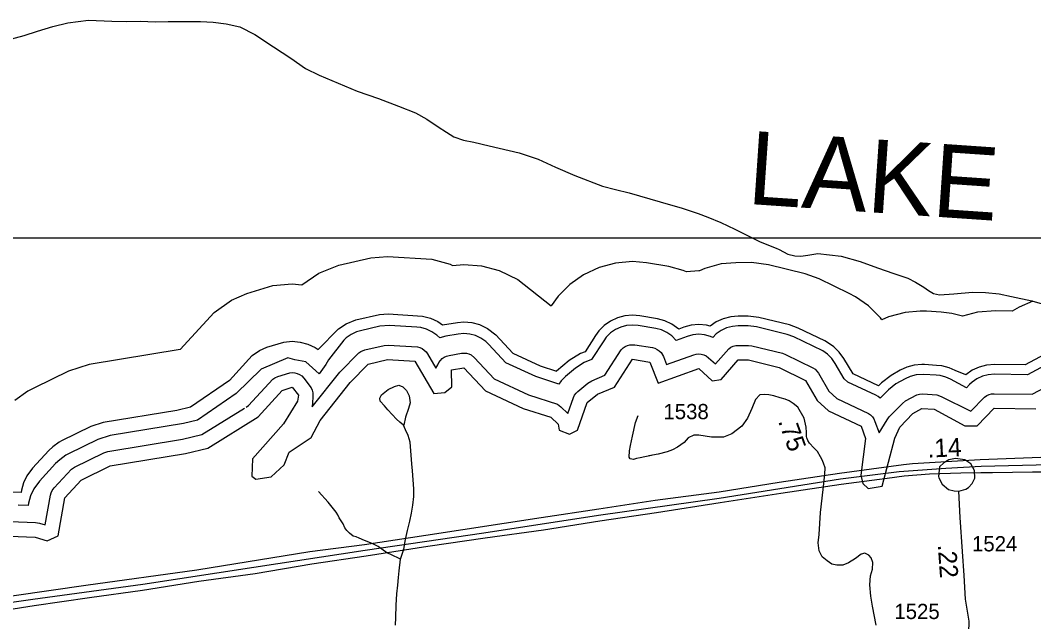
# Model space of a CAD drawing. Extents: x 2290615 to 2522933, y 819489 to 1012715.
# Drawn here: x 2377563 to 2385868, y 993811 to 998744 of the extents above; entities that cross this region are included whole.
import ezdxf

# ---------------------------------------------------------------- set-up
doc = ezdxf.new("R2010")
doc.units = 0
for name, color, linetype in [('Exist Boundary Political CountyLine', 7, 'Continuous'), ('Exist Hydrographic Buffer Line', 7, 'Continuous'), ('Exist Hydrographic Lake Shore', 7, 'Continuous'), ('Exist Hydrographic Lake Shore Label', 7, 'Continuous'), ('Exist Road Non-System Type 51', 7, 'Continuous'), ('Exist Road Secondary Mileage Tenths English Label', 7, 'Continuous'), ('Exist Road Secondary Type 51 Attributed', 7, 'Continuous'), ('Exist Road Secondary Type 51 Number Label', 7, 'Continuous'), ('Exist Utilities Electrical Transmission Line', 7, 'Continuous'), ('Map Preparation Inset Cut Line', 7, 'Continuous')]:
    doc.layers.add(name, color=color, linetype=linetype)

msp = doc.modelspace()

# ---------------------------------------------------------------- linework, layer by layer
at = {"layer": 'Exist Boundary Political CountyLine'}
msp.add_lwpolyline([(2377454.4, 998580.3), (2377594.9, 998620.1), (2377703.5, 998654.6), (2377830, 998693.8), (2377952.9, 998722.9), (2378122.1, 998743.8), (2378312.5, 998737.7), (2378430.7, 998734.5), (2378546.7, 998735.3), (2378671, 998730.4), (2378775, 998732.7), (2378927.1, 998732.9), (2379039.1, 998733.5), (2379145.4, 998727.9), (2379252, 998714.3), (2379363.1, 998688.8), (2379485.8, 998625.8), (2379638, 998526), (2379781.9, 998433.9), (2379901.4, 998348.7), (2380013.8, 998293.3), (2380325.4, 998162), (2380497.9, 998103.1), (2380662.6, 998039.8), (2380801, 997983.5), (2380895.1, 997933.3), (2380987.8, 997869.1), (2381055.7, 997825.8), (2381115.2, 997788.3), (2381196.4, 997761.6), (2381279.2, 997743), (2381406.5, 997714.2), (2381653, 997656.3), (2381807.2, 997604.6), (2381950, 997538.4), (2382106.9, 997470.8), (2382334.7, 997382.1), (2382439.8, 997356.4), (2382553, 997329.1), (2382806.3, 997253.4), (2382988.5, 997202.9), (2383118.3, 997160.2), (2383197.6, 997129.4), (2383305.5, 997083.9), (2383417.8, 997030.4), (2383626.2, 996926.9), (2383756.4, 996874.3), (2383780.9, 996863.3), (2383854.5, 996826.3), (2383911.2, 996810.6), (2383959.3, 996808.6), (2384017, 996816.9), (2384098.4, 996832.3), (2384291.4, 996810.2), (2384445.4, 996764.5), (2384587.5, 996714.3), (2384721.6, 996665.8), (2384837.2, 996628.5), (2384900.6, 996595.1), (2384968.3, 996555.9), (2385005.5, 996527.4), (2385046.5, 996503.1), (2385047.5, 996502.9), (2385097, 996491.1), (2385214.7, 996500), (2385366.2, 996514.2), (2385472.4, 996510.6), (2385584.9, 996501.2), (2385685.9, 996477.3), (2385851.5, 996442.1), (2386260.6, 996324.8)], dxfattribs=at)
at = {"layer": 'Exist Hydrographic Buffer Line'}
for points in [[(2378874.5, 996043.8), (2379151.5, 996348.1), (2379293.4, 996446.9), (2379420.5, 996502.8), (2379631.9, 996567.6), (2379792.2, 996581.9), (2379871.6, 996574.8), (2380009.7, 996671), (2380172.7, 996735.4), (2380436, 996795.5), (2380574, 996806.4), (2380935.7, 996783.3), (2381085.6, 996743.2), (2381106.7, 996733.4), (2381197.7, 996741.2), (2381343.9, 996728.9), (2381486.7, 996690.7), (2381642, 996618.9), (2381912.7, 996402.4)], [(2385556.4, 996361.2), (2385406.4, 996349.3), (2385284.5, 996316.8), (2385197.1, 996340.1), (2385110.8, 996350.2), (2384990.7, 996357.1), (2384938.6, 996358.4), (2384814, 996347.5), (2384679.4, 996311.7), (2384624.3, 996286.2), (2384611.8, 996303.9), (2384513.5, 996402.5), (2384408.4, 996475.9), (2384355.1, 996504.3), (2384109, 996623.9), (2383994.5, 996665.1), (2383695.6, 996738.9), (2383555.5, 996755.9), (2383426.3, 996755.6), (2383308.2, 996745), (2383173.7, 996709.1), (2383128.2, 996687.8), (2383123.3, 996688.2), (2383023.8, 996679.4), (2382995.8, 996692.5), (2382877.5, 996724.1), (2382693.8, 996754.7), (2382579.5, 996764.2), (2382441.8, 996752.2), (2382306.7, 996716.1), (2382180.2, 996657), (2382066.1, 996577), (2381971.3, 996482.2), (2381912.7, 996402.4)], [(2385860.6, 996439.5), (2385748.8, 996389.6), (2385691.2, 996359), (2385556.4, 996361.2)], [(2379276.7, 995788.9), (2379462.8, 995993.3), (2379524, 996035.9), (2379584.2, 996062.4), (2379722.3, 996104.7), (2379792.2, 996110.9), (2379857.6, 996105.1), (2379920.4, 996088.3), (2379979.7, 996060.9), (2380005, 996043.2), (2380172.1, 996212.4), (2380233, 996254.8), (2380311.9, 996286), (2380507, 996330.5), (2380577.5, 996336.1), (2380859.4, 996318.2), (2380925.3, 996300.5), (2380984.6, 996273.1), (2381024.6, 996245.3), (2381145.5, 996265.9), (2381198.1, 996270.5), (2381263, 996265), (2381326.4, 996248), (2381393.5, 996217), (2381459.8, 996163.9), (2381599.7, 996014), (2381822.9, 995909.9), (2381958, 995866.2)], [(2385549.2, 995921.3), (2385480.8, 995915.8), (2385420.1, 995899.6), (2385363.3, 995873.1), (2385311.8, 995837.1), (2385224.5, 995870.3), (2385175.5, 995892.5), (2385114.8, 995908.7), (2385072.7, 995913.7), (2384972.7, 995919.4), (2384952.2, 995919.9), (2384889.8, 995914.5), (2384828.9, 995898.3), (2384775, 995873.3), (2384700, 995830.8), (2384619.8, 995769.2), (2384596.8, 995745.5), (2384389.1, 995843.8), (2384311.6, 995969.3), (2384275.1, 996021.3), (2384230.8, 996065.7), (2384179.3, 996101.7), (2384156.6, 996113.8), (2383938.6, 996219.7), (2383867.4, 996245.3), (2383616.5, 996307.3), (2383529.5, 996317.8), (2383446.5, 996317.6), (2383384.8, 996312.1), (2383324.1, 996295.9), (2383267.3, 996269.3), (2383217.4, 996234.6), (2383185.9, 996243), (2383123.3, 996248.5), (2383060.8, 996243), (2383000.1, 996226.8), (2382958.7, 996211.6), (2382902.3, 996252.7), (2382845.5, 996279.3), (2382784.8, 996295.5), (2382639.6, 996319.7), (2382580.3, 996324.6), (2382517.8, 996319.2), (2382457.1, 996303), (2382400.3, 996276.4), (2382348.8, 996240.3), (2382304.5, 996196), (2382277.3, 996158.9), (2382191.3, 996024.8), (2382154.8, 996009.7), (2382060.3, 995952.4), (2381958, 995866.2)], [(2382030, 995822.1), (2381995.7, 995788), (2381976.5, 995760.5), (2381787.8, 995821.3), (2381543, 995935.7), (2381402.9, 996085.6), (2381378.3, 996109.1), (2381338.3, 996137.1), (2381294, 996157.7), (2381246.7, 996170.3), (2381198.3, 996174.6), (2381150.7, 996170.5), (2381050.8, 996153.4), (2381002.5, 996140.6), (2380977.2, 996161.6), (2380937.2, 996189.6), (2380893, 996210.2), (2380845.8, 996222.8), (2380814.2, 996226.6), (2380589.3, 996240.3), (2380509.9, 996233.8), (2380352, 996197.7), (2380318.6, 996187.8), (2380274.3, 996167.2), (2380234.3, 996139.2), (2380214.4, 996121), (2380088.9, 995959.7), (2380067.5, 995920.4), (2380013.9, 995845.4), (2379903.2, 995941.9), (2379813.9, 995959.7), (2379756.7, 995974), (2379538.8, 995881.1), (2379333.6, 995682.3)], [(2385993.4, 995930.8), (2385817.5, 995836.9), (2385547.8, 995841.3), (2385494.7, 995837.1), (2385447.6, 995824.5), (2385403.3, 995803.9), (2385363.3, 995775.9), (2385342, 995756.1), (2385316.3, 995729.3), (2385186.3, 995800.1), (2385148, 995817.4), (2385100.8, 995830), (2385068.2, 995833.8), (2384968.2, 995839.5), (2384903.8, 995835.8), (2384856.6, 995823), (2384814.2, 995803.7), (2384739.3, 995761.2), (2384677, 995713.2), (2384611, 995645.6), (2384594.4, 995657.3), (2384574.1, 995667.9), (2384344, 995776.7), (2384314.3, 995803.9), (2384242.1, 995929.5), (2384213.8, 995970), (2384179.3, 996004.4), (2384139.3, 996032.4), (2383903.7, 996147.7), (2383848.2, 996167.7), (2383597.2, 996229.7), (2383529.5, 996237.9), (2383446.5, 996237.7), (2383398.7, 996233.3), (2383351.5, 996220.7), (2383307.2, 996200.1), (2383267.3, 996172.1), (2383237.5, 996143), (2383219.1, 996151.6), (2383171.7, 996164.2), (2383123.3, 996168.4), (2383074.7, 996164.2), (2383027.6, 996151.6), (2382938.4, 996118.8), (2382902.3, 996155.4), (2382862.3, 996183.4), (2382818, 996204), (2382770.8, 996216.6), (2382626.3, 996240.8), (2382580.3, 996244.6), (2382531.7, 996240.3), (2382484.6, 996227.7), (2382440.3, 996207.1), (2382400.3, 996179.1), (2382365.8, 996144.6), (2382344.5, 996115.7), (2382245.1, 995960.5), (2382185.2, 995935.8), (2382112, 995891.2), (2382030, 995822.1)], [(2379414.2, 995570.7), (2379434.4, 995583.3), (2379632.1, 995800.5), (2379649.3, 995812.5), (2379673.1, 995822.9), (2379771.5, 995853.1), (2379792.2, 995854.9), (2379812.9, 995853.1), (2379833.2, 995847.6), (2379852.3, 995838.8), (2379869.5, 995826.8), (2379887.8, 995807.8), (2379947.3, 995728.1), (2379956.1, 995709.2), (2379961.6, 995688.9), (2379961.8, 995649.1), (2379954.4, 995572.4), (2380180.8, 995858.3), (2380337.1, 996016.6), (2380354.3, 996028.6), (2380387.5, 996041.7), (2380545.6, 996077.8), (2380579.4, 996080.5), (2380817.9, 996065.3), (2380838.2, 996059.9), (2380857.3, 996051.1), (2380874.5, 996039.1), (2380889.3, 996024.2), (2380900.8, 996007.7), (2380968.8, 995891.6), (2380985.4, 995918.5), (2380994.3, 995937.4), (2381006.4, 995954.5), (2381020.9, 995969.3), (2381038.3, 995981.3), (2381057.2, 995990.2), (2381077.9, 995995.7), (2381178, 996012.8), (2381198.3, 996014.6), (2381219, 996012.8), (2381239.3, 996007.4), (2381258.4, 995998.6), (2381286, 995976.4), (2381447, 995803.9), (2381729.4, 995672.1), (2381965.5, 995595.8)], [(2381965.5, 995595.8), (2381994.3, 995573.9), (2382051.3, 995518.4), (2382097.4, 995649.1), (2382106.3, 995668), (2382118.3, 995685.1), (2382133.1, 995699.8), (2382214.9, 995768.8), (2382246.5, 995787.9), (2382352.5, 995831.9), (2382488.3, 996041.7), (2382503, 996056.6), (2382520.3, 996068.6), (2382539.3, 996077.4), (2382559.4, 996082.8), (2382600, 996082.9), (2382742.9, 996059.2), (2382763.2, 996053.7), (2382782.3, 996044.9), (2382799.5, 996032.9), (2382814.3, 996018), (2382833.8, 995985), (2382859.8, 995919.5), (2383082.3, 996001.2), (2383102.6, 996006.7), (2383123.3, 996008.5), (2383144, 996006.7), (2383164.3, 996001.2), (2383183.2, 995992.4), (2383204.5, 995976.7), (2383260.1, 995925.7), (2383370, 996049.5), (2383387.2, 996061.5), (2383406.3, 996070.3), (2383426.6, 996075.8), (2383447.1, 996077.6), (2383529.9, 996077.8), (2383559, 996074.3), (2383810, 996012.4), (2383833.8, 996003.8), (2384059.2, 995893.9), (2384076.6, 995881.9), (2384091.4, 995867), (2384103.3, 995849.8)], [(2378874.5, 996043.8), (2378128.1, 995921.5), (2377958.3, 995866.9), (2377678.8, 995729.2), (2377625.4, 995700.7), (2377518.6, 995626.3)], [(2387101.5, 995425.1), (2386995.3, 995439.5), (2386753.3, 995436.2), (2386709.5, 995432), (2386684, 995486.5), (2386647.9, 995537.9), (2386589.5, 995724.5), (2386580.5, 995752.7), (2386554, 995809.5), (2386517.9, 995860.9), (2386473.9, 995905.3), (2386422.2, 995941.2), (2386393.7, 995956.1), (2386276.8, 996010.5), (2386248.5, 996022.1), (2386187.8, 996038.2), (2386125.3, 996043.8), (2386062.7, 996038.2), (2386002, 996022.1), (2385955.7, 996001.4), (2385798, 995917.3), (2385549.2, 995921.3)], [(2384103.3, 995849.8), (2384187.9, 995702.5), (2384253.8, 995642.3), (2384514.2, 995518.7), (2384531.6, 995506.6), (2384546.4, 995491.9), (2384558.3, 995474.8), (2384567.5, 995454.3), (2384602.6, 995359.7), (2384666.3, 995468.1), (2384684.6, 995492), (2384791.6, 995601.4), (2384818.3, 995622), (2384911.4, 995672.7), (2384931.5, 995678.2), (2384958.9, 995679.8), (2385072.9, 995672.4), (2385109.9, 995659.6), (2385353, 995537.3), (2385466, 995653.3), (2385483.3, 995665.2), (2385502.3, 995674.1), (2385522.4, 995679.5), (2385545.2, 995681.3), (2385856.2, 995676.2), (2386084.3, 995796.5)], [(2379276.7, 995788.9), (2378959.1, 995570.3), (2378845.3, 995543.2), (2378243.1, 995444.5), (2378142.2, 995412.1), (2377902.3, 995293.9), (2377881.4, 995282.7), (2377829.7, 995246.7), (2377796.5, 995214.9), (2377664.6, 995071.6), (2377617.5, 995007.7), (2377591, 994950.8), (2377574.8, 994890.3), (2377571.3, 994870.2), (2377488.9, 994873.2)], [(2379333.6, 995682.3), (2379015.9, 995463.7), (2378902.1, 995436.6), (2378299.9, 995337.9), (2378199, 995305.5), (2377959.1, 995187.3), (2377938.2, 995176.1), (2377886.5, 995140.1), (2377853.3, 995108.2), (2377721.5, 994965), (2377674.3, 994901.1), (2377647.8, 994844.2), (2377631.6, 994783.6), (2377628.2, 994763.5), (2377545.7, 994766.6)], [(2377768.8, 994604.6), (2377811, 994848.5), (2377816.6, 994868.7), (2377825.4, 994887.7), (2377841, 994909), (2377984.1, 995062.9), (2378008.3, 995078.6), (2378248.2, 995196.8), (2378281.8, 995207.7), (2378892.5, 995307.8), (2379052.6, 995345.9), (2379400, 995561.9)], [(2377479.9, 994633.4), (2377688.8, 994625.6), (2377720.8, 994620), (2377768.8, 994604.6)]]:
    msp.add_lwpolyline(points, dxfattribs=at)
at = {"layer": 'Exist Hydrographic Lake Shore'}
for points in [[(2377475.4, 994513.5), (2377684.3, 994505.7), (2377784.4, 994473.7), (2377875.2, 994516.9), (2377929.3, 994827.7), (2378061.2, 994970.9), (2378301.3, 995089.3), (2378916.3, 995190), (2379099.4, 995233.7), (2379512.3, 995490.3), (2379709.2, 995708.5), (2379792.2, 995735), (2379843.3, 995668.1), (2379835.3, 995618.6), (2379721.3, 995433.3), (2379466.2, 995147.1), (2379460.3, 995005.6), (2379494.3, 994980.7), (2379618.4, 994999), (2379725.2, 995098.6), (2379766.2, 995202), (2379947.3, 995321.1), (2380020.3, 995462), (2380266.3, 995774.2), (2380414.2, 995924.7), (2380572.3, 995960.7), (2380797.2, 995947.1), (2380951.2, 995684.1), (2381042.2, 995691.2), (2381100.3, 995736.3), (2381098.2, 995877.4), (2381198.3, 995894.6), (2381375.2, 995704.9), (2381685.3, 995560.2), (2381911.2, 995487.4), (2381970.3, 995430.7), (2381979.3, 995381.9), (2382063.2, 995349.2), (2382130.2, 995381.4), (2382210.2, 995607.9), (2382292.2, 995677), (2382433.3, 995735.4)], [(2382433.3, 995735.4), (2382580.3, 995964.6), (2382722.2, 995940.9), (2382791.3, 995766.4), (2383123.3, 995888.4), (2383232.2, 995788), (2383307.2, 995797.6), (2383447.3, 995957.7), (2383530.3, 995957.8), (2383781.3, 995895.8), (2383999.3, 995789.9), (2384093.2, 995626.4), (2384186.3, 995541.6), (2384454.3, 995414.8), (2384489.4, 995314.4), (2384451.2, 995014), (2384468.2, 994945.8), (2384510.3, 994904.9), (2384627.4, 994922.8), (2384730.3, 995317.8), (2384770.3, 995408.1), (2384877.3, 995517.5), (2384952.2, 995560), (2385052.2, 995554.2), (2385304.2, 995416.9), (2385404.3, 995417.6), (2385543.3, 995561.3), (2385885.4, 995555.8)]]:
    msp.add_lwpolyline(points, dxfattribs=at)
at = {"layer": 'Exist Road Non-System Type 51'}
for points in [[(2380680.1, 994324.9), (2380705.3, 994406.4), (2380720.3, 994484.7), (2380736.4, 994559.6), (2380756, 994636.4), (2380769.8, 994702), (2380779, 994767.7), (2380788.2, 994837.6), (2380788.2, 994902.1), (2380777.8, 995048.1), (2380773.2, 995105.7), (2380757.1, 995284.2), (2380741.1, 995337.8), (2380720.3, 995386.2), (2380704.2, 995424.2), (2380673.2, 995448.3), (2380646.7, 995473.7), (2380576.5, 995549.7), (2380547.7, 995582), (2380513.2, 995620), (2380509.7, 995644.1), (2380523.5, 995671.8), (2380578.8, 995715.6), (2380629.4, 995740.9), (2380666.3, 995750.1), (2380699.6, 995736.3), (2380727.3, 995707.5), (2380749.1, 995662.6), (2380757.2, 995607.3), (2380744.5, 995560.1), (2380720.3, 995488.7), (2380705.4, 995424.2)], [(2382736.8, 995174.4), (2382681.6, 995163.6), (2382642.5, 995155.6), (2382612.6, 995149.8), (2382587.3, 995141.7), (2382562, 995147.5), (2382552.8, 995160.2), (2382555.1, 995213.1), (2382564.3, 995256.8), (2382580.4, 995333.9), (2382605.7, 995445.6), (2382627.5, 995502)], [(2380680.1, 994324.9), (2380599.4, 994361.6), (2380567.2, 994376.6), (2380495.8, 994427.3), (2380447.5, 994452.6), (2380384.3, 994476.6), (2380341.8, 994495.1), (2380316.4, 994506.6), (2380292.3, 994513.5), (2380261.4, 994536.4), (2380238.3, 994559.4), (2380222.2, 994582.4), (2380208.4, 994613.5), (2380177.5, 994664), (2380166, 994688.2), (2380151, 994708.9), (2380085.5, 994791.7), (2380006.1, 994879.2)], [(2380637.5, 993782.1), (2380641, 993846.6), (2380643.3, 993948), (2380649, 994038.6), (2380657.1, 994111.1), (2380661.7, 994174.5), (2380668.6, 994229.8), (2380680.1, 994324.9)]]:
    msp.add_lwpolyline(points, dxfattribs=at)
at = {"layer": 'Exist Road Secondary Type 51 Attributed'}
for points in [[(2384578.1, 993781.7), (2384548.2, 993937.6), (2384532.1, 994020.5), (2384525.2, 994115), (2384529.8, 994186.4), (2384545.9, 994241.7), (2384550.5, 994296.9), (2384536.7, 994333.8), (2384518.3, 994356.8), (2384484.4, 994373.2), (2384453.3, 994364), (2384407.3, 994329.5), (2384350.9, 994293.7), (2384303.7, 994275.3), (2384254.2, 994274.2), (2384215.1, 994284.5), (2384174.8, 994309.9), (2384133.3, 994343.3), (2384109.2, 994392.8), (2384101.1, 994457.3), (2384109.2, 994525.3), (2384121.8, 994706.7), (2384143.7, 994895), (2384156.4, 995022.6), (2384158.7, 995072.2), (2384146, 995110.2), (2384135.7, 995139), (2384121.9, 995163.1), (2384095.4, 995206.9), (2384065.5, 995236.9), (2384031.7, 995276.2), (2384017.3, 995296.7), (2384009.1, 995319.3), (2384007.1, 995329.6), (2384005, 995362.5), (2384003, 995407.7), (2383986.5, 995479.6), (2383935.2, 995570), (2383898.2, 995600.8), (2383865.4, 995623.4), (2383830.5, 995635.8), (2383791.4, 995648.1), (2383738.1, 995662.5), (2383697, 995672.7), (2383658, 995674.8), (2383625.1, 995670.7), (2383588.1, 995633.7), (2383557.3, 995559.7), (2383522.4, 995481.6), (2383475.2, 995413.8), (2383395.1, 995352.2), (2383325.3, 995325.5), (2383226.7, 995325.5), (2383124, 995341.9), (2383083, 995341.9), (2383037.8, 995319.3), (2383002.9, 995282.3), (2382949.5, 995243.3), (2382908.4, 995220.7), (2382863.2, 995204.2), (2382791.4, 995185.7), (2382713.3, 995171.4)], [(2385158.6, 995131.1), (2385131.2, 995115.4), (2385096.8, 995080.3), (2385086.7, 995000.9), (2385091.3, 994991.8)], [(2385253.8, 994880.7), (2385310.5, 994899.6), (2385334.6, 994913), (2385364.8, 994945.8), (2385377.1, 994972), (2385384.5, 994989.1), (2385383.4, 995050.6), (2385352, 995106.3), (2385303.4, 995139.7), (2385226.4, 995149.9), (2385173.8, 995139.7), (2385158.6, 995131.1)], [(2385091.3, 994991.8), (2385118.5, 994938.6), (2385171, 994895), (2385217.6, 994884.1), (2385253.8, 994880.7)], [(2385337.5, 993719.4), (2385338.4, 993815.8), (2385308.5, 993995.5), (2385299.3, 994189), (2385285.5, 994387.1), (2385264.8, 994664.6), (2385253.8, 994880.7)]]:
    msp.add_lwpolyline(points, dxfattribs=at)
at = {"layer": 'Exist Utilities Electrical Transmission Line'}
for points in [[(2376770.2, 993866.9), (2377666.4, 993994.9), (2378568.5, 994118.8), (2379476.7, 994258.8), (2380388.7, 994399), (2381362.7, 994539.9), (2382302.4, 994686.4), (2383290.6, 994823.5), (2384284.2, 994982.6), (2384765.4, 995043), (2385147, 995069.9), (2385436.7, 995085.8), (2386000.5, 995099.4)], [(2385927.6, 995158.3), (2385429.9, 995137.8), (2384874.5, 995106.4), (2384800.6, 995097.3), (2384275.6, 995026.5), (2383782.8, 994952), (2383289.9, 994873.5), (2382766.8, 994806.6), (2382303.8, 994734.3), (2381830.9, 994662), (2380886.9, 994517.5), (2380384, 994440.8), (2379936.9, 994383), (2379009, 994234.8), (2378100.8, 994108.6), (2377206.6, 993978.8)], [(2377228, 993873.2), (2377677.1, 993945.1), (2378130.1, 994011.1), (2378565.3, 994070.8), (2379026.2, 994142.8), (2379489.2, 994207.1), (2379952.2, 994287.2), (2380399.2, 994351.2), (2380902.1, 994429.7), (2381373.1, 994500.1), (2381852.2, 994564.4), (2382313.2, 994638.4), (2382778.1, 994706.6), (2383299.1, 994787.6), (2383795.9, 994866.1), (2384290.8, 994938.7), (2384668.2, 994989.6), (2384805.9, 995007.5), (2385013.6, 995024.2), (2385271.4, 995031.6), (2385435.4, 995033.8), (2385529.4, 995035), (2385859.3, 995039.4), (2386001.3, 995041.4)]]:
    msp.add_lwpolyline(points, dxfattribs=at)
at = {"layer": 'Map Preparation Inset Cut Line'}
msp.add_lwpolyline([(2369931.7, 996959.3), (2400125.8, 996959.3), (2403337.9, 985770.4), (2415972.3, 978275.4), (2416025.8, 958413.7), (2369771.1, 958413.7)], close=True, dxfattribs=at)

# ---------------------------------------------------------------- texts
at = {"layer": 'Exist Hydrographic Lake Shore Label'}
msp.add_text('LAKE', height=600, rotation=356.09507, dxfattribs=at).set_placement((2383513.2, 997238.5))
at = {"layer": 'Exist Road Secondary Mileage Tenths English Label'}
for s, rotation, p in [('.75', 289.78657, (2383772, 995455.6)), ('.14', 2.75003, (2385001.4, 995156.7)), ('.22', 273.9881, (2385081.9, 994442.4))]:
    msp.add_text(s, height=150, rotation=rotation, dxfattribs=at).set_placement(p)
at = {"layer": 'Exist Road Secondary Type 51 Number Label'}
for s, p in [('1538', (2382833.5, 995472.1)), ('1524', (2385362.3, 994388)), ('1525', (2384725.9, 993832.9))]:
    msp.add_text(s, height=125, dxfattribs=at).set_placement(p)

doc.saveas('drawing.dxf')
